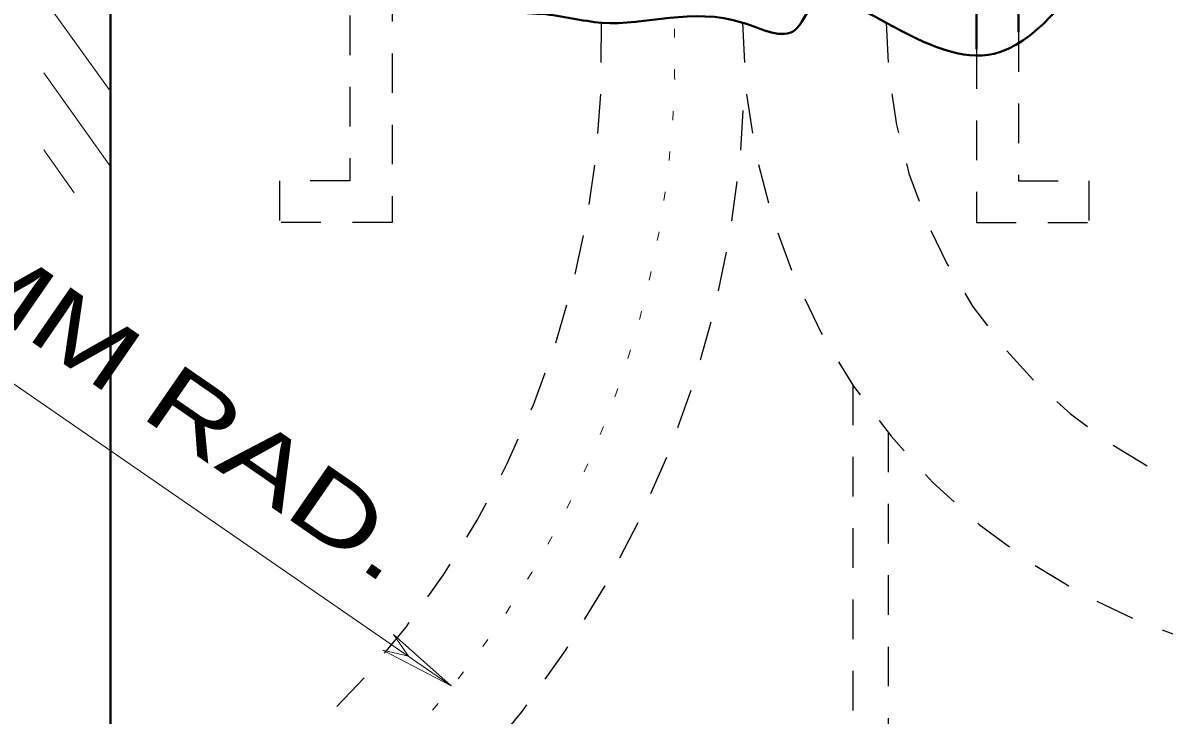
# Model space of a CAD drawing. Extents: x 312583 to 312854, y 144419 to 144597.
# Drawn here: x 312777.02 to 312789.97, y 144530.33 to 144538.19 of the extents above; entities that cross this region are included whole.
import ezdxf

# ---------------------------------------------------------------- set-up
doc = ezdxf.new("R2010")
doc.units = 0
doc.header["$LTSCALE"] = 0.3
doc.linetypes.add('DOTTED', pattern=[1.5, 0.3, -1.2])
doc.linetypes.add('SHORT_DASHED', pattern=[2.7, 1.5, -1.2])
doc.layers.add('1', color=7, linetype='Continuous', lineweight=25)
doc.layers.add('2', color=7, linetype='Continuous', lineweight=13)

msp = doc.modelspace()

# ---------------------------------------------------------------- linework, layer by layer
at = {"layer": '1', "linetype": 'DOTTED', "lineweight": 13}
msp.add_line((312784.4183, 144537.5619), (312784.4183, 144544.5539), dxfattribs=at)
at = {"layer": '1', "lineweight": 40}
for p, q in [((312778.0166, 144543.5879), (312778.0166, 144521.2243)), ((312787.8453, 144542.6986), (312787.8453, 144537.8916)), ((312788.3206, 144542.6986), (312788.3206, 144538.0833))]:
    msp.add_line(p, q, dxfattribs=at)
at = {"layer": '1', "linetype": 'SHORT_DASHED'}
for p, q in [((312780.7306, 144539.8926), (312780.7306, 144536.3966)), ((312781.2136, 144539.4633), (312781.2136, 144535.9213)), ((312788.3206, 144538.0833), (312788.3206, 144536.3966)), ((312787.8453, 144537.8916), (312787.8453, 144535.9213)), ((312781.2136, 144535.9213), (312779.9333, 144535.9213)), ((312787.8453, 144535.9213), (312789.118, 144535.9213)), ((312786.4423, 144534.0736), (312786.4423, 144521.2243)), ((312786.841, 144533.5369), (312786.841, 144521.2243))]:
    msp.add_line(p, q, dxfattribs=at)
for points in [[(312780.7306, 144536.3966), (312779.9333, 144536.3966), (312779.9333, 144535.9213)], [(312788.3206, 144536.3966), (312789.118, 144536.3966), (312789.118, 144535.9213)]]:
    msp.add_lwpolyline(points, dxfattribs=at)
for centre, radius, start, end in [((312772.9074, 144537.8539), 10.6854, 298.57546, 1.79804), ((312792.5686, 144538.1893), 7.3792, 180, 270), ((312792.5686, 144538.1893), 5.75, 180, 270), ((312772.9074, 144537.8539), 12.3146, 294.52268, 358.54105)]:
    msp.add_arc(centre, radius, start, end, dxfattribs=at)
at = {"layer": '1', "linetype": 'DOTTED', "lineweight": 13}
msp.add_arc((312772.9074, 144537.8539), 11.516, 273.78468, 358.54081, dxfattribs=at)
at = {"layer": '1', "lineweight": 40}
msp.add_spline([(312779.55, 144544.2089), (312779.757, 144543.5879), (312779.8413, 144540.9813), (312780.3013, 144540.2836), (312780.8073, 144539.8236), (312781.3746, 144539.3099), (312782.0723, 144538.7503), (312782.5016, 144538.3439), (312782.908, 144538.2903), (312783.5903, 144538.1906), (312785.1926, 144538.1906), (312785.783, 144538.1063), (312785.9746, 144538.3746), (312786.818, 144538.1906), (312788.0446, 144537.8379), (312789.256, 144538.9113), (312790.061, 144539.6933), (312791.349, 144540.6286), (312793.235, 144542.0316), (312794.3083, 144543.4576), (312794.523, 144543.9406), (312795.0136, 144544.2243)], degree=3, dxfattribs=at)
at = {"layer": '2'}
for p, q in [((312777.2576, 144538.4666), (312778.0013, 144537.4316)), ((312771.017, 144538.1599), (312781.8806, 144530.6619)), ((312777.2576, 144537.6233), (312778.0166, 144536.5576)), ((312777.2576, 144536.7493), (312777.6026, 144536.2586)), ((312781.229, 144531.2446), (312781.3976, 144530.9993)), ((312781.8806, 144530.6619), (312781.229, 144531.2446)), ((312781.1063, 144531.0683), (312781.3976, 144530.9993)), ((312781.8806, 144530.6619), (312781.1063, 144531.0683))]:
    msp.add_line(p, q, dxfattribs=at)

# ---------------------------------------------------------------- texts
at = {"layer": '2', "width": 1.4}
msp.add_text('508 MM RAD.   ', height=0.76, rotation=325.387, dxfattribs=at).set_placement((312773.7786, 144536.8739))

doc.saveas('drawing.dxf')
